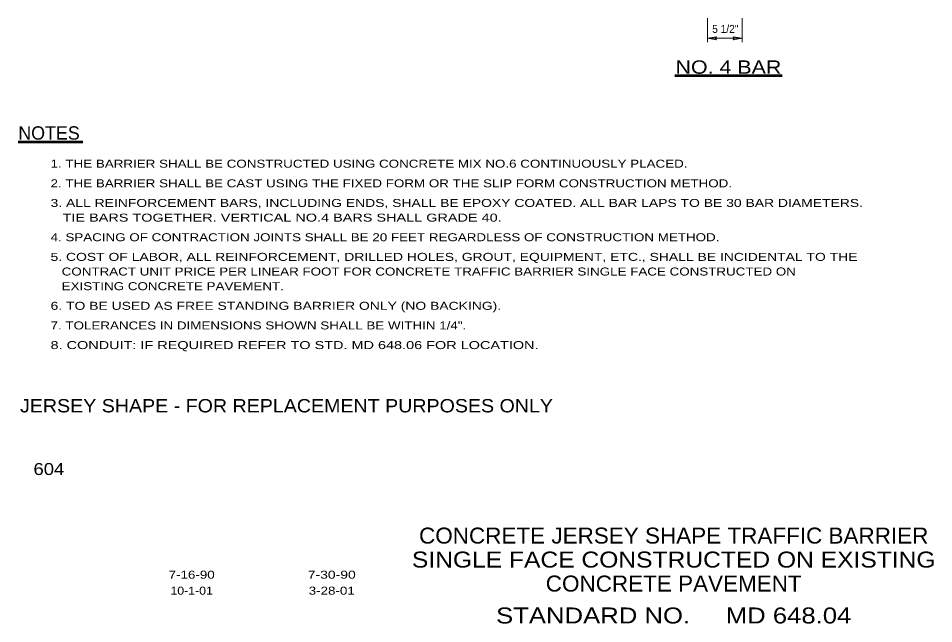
# Model space of a CAD drawing. Extents: x 2.21 to 9.21, y 11.59 to 21.05.
# Drawn here: x 2.21 to 9.08, y 11.59 to 16.14 of the extents above; entities that cross this region are included whole.
import ezdxf
from ezdxf.enums import TextEntityAlignment as Align

# ---------------------------------------------------------------- set-up
doc = ezdxf.new("R2010")
doc.units = 0
doc.header["$LTSCALE"] = 0.024
for name, color, linetype, lineweight in [('10', 7, 'Continuous', 13), ('12', 7, 'Continuous', 53), ('13', 7, 'Continuous', 53)]:
    doc.layers.add(name, color=color, linetype=linetype, lineweight=lineweight)

msp = doc.modelspace()

# ---------------------------------------------------------------- linework, layer by layer
at = {"layer": '10'}
for p, q in [((7.3795, 16.13517), (7.3795, 15.95667)), ((7.6385, 16.13517), (7.6385, 15.95667)), ((7.44667, 15.99667), (7.3795, 15.9855)), ((7.44667, 15.99667), (7.43817, 15.9855)), ((7.57133, 15.99667), (7.6385, 15.9855)), ((7.57133, 15.99667), (7.57967, 15.9855)), ((7.3795, 15.9855), (7.6385, 15.9855)), ((7.44667, 15.97433), (7.3795, 15.9855)), ((7.44667, 15.97433), (7.43817, 15.9855)), ((7.57133, 15.97433), (7.6385, 15.9855)), ((7.57133, 15.97433), (7.57967, 15.9855))]:
    msp.add_line(p, q, dxfattribs=at)
at = {"layer": '12'}
msp.add_line((7.1345, 15.7065), (7.939, 15.7065), dxfattribs=at)
at = {"layer": '13'}
msp.add_line((2.211, 15.20733), (2.69467, 15.20733), dxfattribs=at)

# ---------------------------------------------------------------- texts
at = {"layer": '12'}
for s, height, width, p in [('5 1/2"', 0.06001, 0.95, (7.51321, 16.0255)), ('NO. 4 BAR', 0.1, 1.2, (7.53675, 15.71908))]:
    msp.add_text(s, height=height, dxfattribs=dict(at, width=width)).set_placement(p, align=Align.CENTER)
at = {"layer": '12', "width": 1.1}
msp.add_text('JERSEY SHAPE - FOR REPLACEMENT PURPOSES ONLY', height=0.1, dxfattribs=at).set_placement((2.22367, 13.177))
at = {"layer": '13'}
msp.add_text('NOTES', height=0.1, dxfattribs=at).set_placement((2.211, 15.22442))
for s, width, p in [('1. THE BARRIER SHALL BE CONSTRUCTED USING CONCRETE MIX NO.6 CONTINUOUSLY PLACED.', 1.25, (2.45283, 15.01375)), ('2. THE BARRIER SHALL BE CAST USING THE FIXED FORM OR THE SLIP FORM CONSTRUCTION METHOD.', 1.25, (2.45283, 14.86642)), ('3. ALL REINFORCEMENT BARS, INCLUDING ENDS, SHALL BE EPOXY COATED. ALL BAR LAPS TO BE 30 BAR DIAMETERS.', 1.3, (2.45283, 14.71908)), ('   TIE BARS TOGETHER. VERTICAL NO.4 BARS SHALL GRADE 40.', 1.35, (2.45283, 14.609)), ('4. SPACING OF CONTRACTION JOINTS SHALL BE 20 FEET REGARDLESS OF CONSTRUCTION METHOD.', 1.25, (2.45283, 14.46167)), ('5. COST OF LABOR, ALL REINFORCEMENT, DRILLED HOLES, GROUT, EQUIPMENT, ETC., SHALL BE INCIDENTAL TO THE', 1.3, (2.45283, 14.31433)), ('   CONTRACT UNIT PRICE PER LINEAR FOOT FOR CONCRETE TRAFFIC BARRIER SINGLE FACE CONSTRUCTED ON', 1.25, (2.45283, 14.20433)), ('   EXISTING CONCRETE PAVEMENT.', 1.25, (2.45283, 14.09433)), ('6. TO BE USED AS FREE STANDING BARRIER ONLY (NO BACKING).', 1.3, (2.45283, 13.947)), ('7. TOLERANCES IN DIMENSIONS SHOWN SHALL BE WITHIN 1/4".', 1.25, (2.45283, 13.79967)), ('8. CONDUIT: IF REQUIRED REFER TO STD. MD 648.06 FOR LOCATION.', 1.35, (2.45283, 13.65225))]:
    msp.add_text(s, height=0.06001, dxfattribs=dict(at, width=width)).set_placement(p)
for s, height, width, p in [('604', 0.09001, 1.15, (2.44029, 12.707)), ('CONCRETE JERSEY SHAPE TRAFFIC BARRIER', 0.12, 1.05, (7.12633, 12.19225)), ('SINGLE FACE CONSTRUCTED ON EXISTING', 0.12, 1.15, (7.12629, 12.01225)), ('7-16-90', 0.06, 1.25, (3.511, 11.92875)), ('7-30-90', 0.06, 1.3, (4.56175, 11.92875)), ('CONCRETE PAVEMENT', 0.12, 1.05, (7.12637, 11.83225)), ('10-1-01', 0.06, 1.15, (3.511, 11.80875)), ('3-28-01', 0.06, 1.25, (4.56171, 11.80875)), ('STANDARD NO.     MD 648.04', 0.12, 1.2, (7.12629, 11.59258))]:
    msp.add_text(s, height=height, dxfattribs=dict(at, width=width)).set_placement(p, align=Align.CENTER)

doc.saveas('drawing.dxf')
